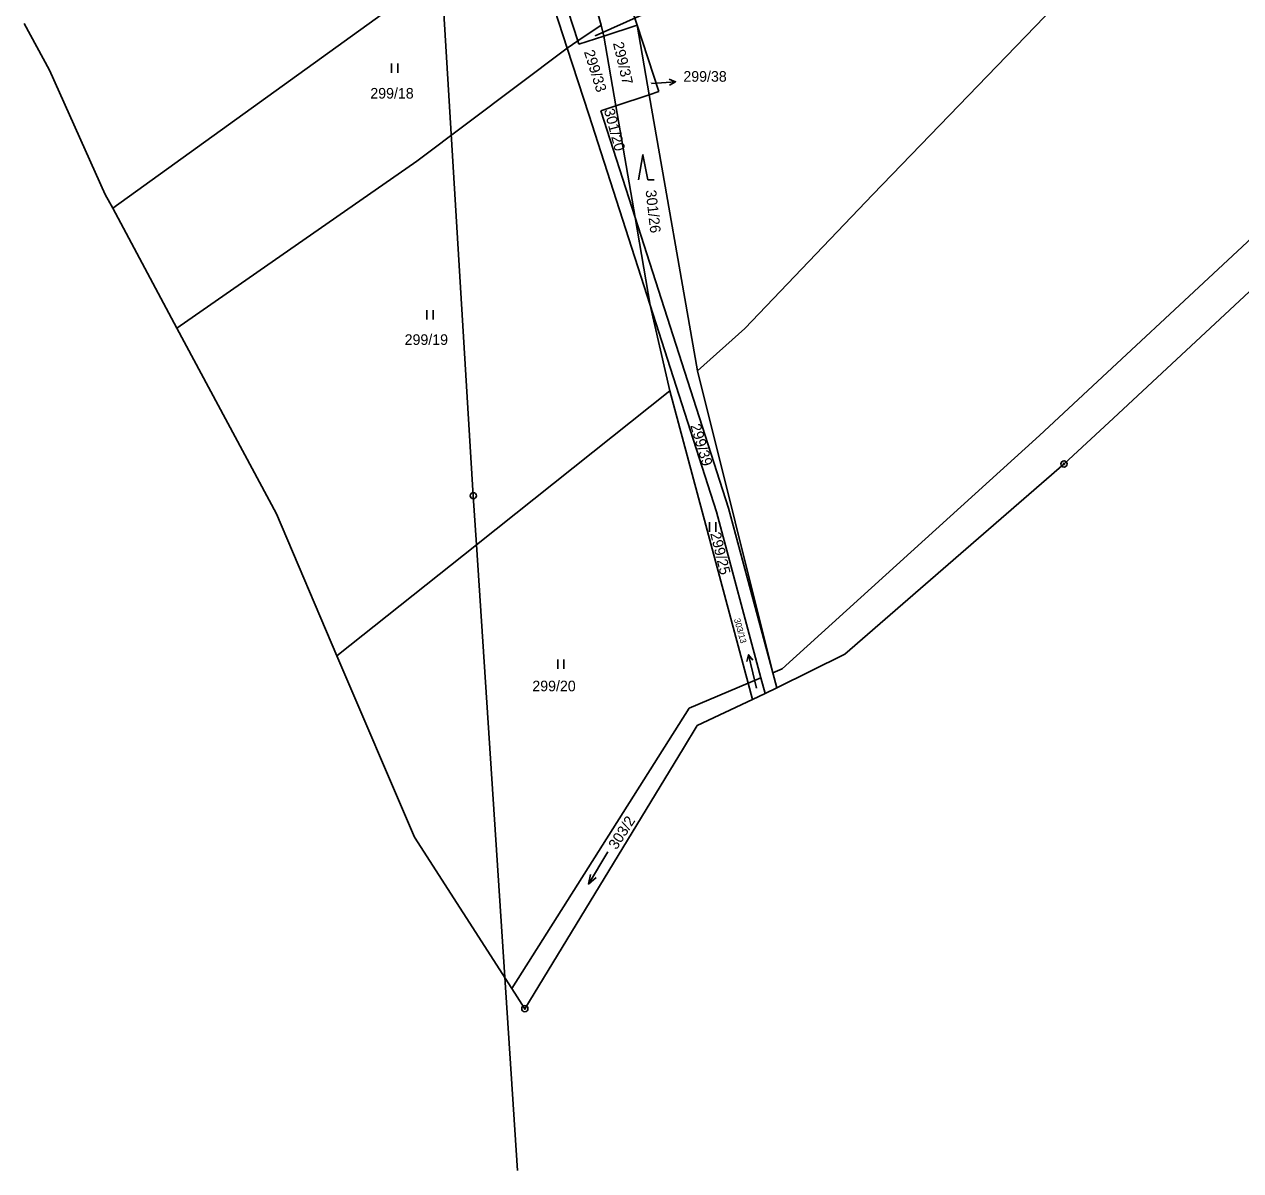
# Model space of a CAD drawing. Extents: x -762263 to -760336, y -1154405 to -1152076.
# Drawn here: x -761484.5 to -761289.6, y -1154141.1 to -1153957.5 of the extents above; entities that cross this region are included whole.
import ezdxf

# ---------------------------------------------------------------- set-up
doc = ezdxf.new("R2010")
doc.units = 0
for name, color, linetype in [('Vrstva 1', 7, 'Continuous'), ('Vrstva 12', 7, 'Continuous'), ('Vrstva 13', 7, 'Continuous'), ('Vrstva 16', 7, 'Continuous'), ('Vrstva 18', 7, 'Continuous'), ('Vrstva 24', 7, 'Continuous'), ('Vrstva 25', 7, 'Continuous'), ('Vrstva 26', 7, 'Continuous'), ('Vrstva 6', 7, 'Continuous'), ('Vrstva 62', 7, 'Continuous')]:
    doc.layers.add(name, color=color, linetype=linetype)

msp = doc.modelspace()

# ---------------------------------------------------------------- linework, layer by layer
at = {"layer": 'Vrstva 1'}
for p, q in [((-761402.87, -1153938.33), (-761395.8, -1153960.17)), ((-761404.57, -1153939.56), (-761397.52, -1153961.33)), ((-761391.66, -1153959.41), (-761386.31, -1153957.66)), ((-761386.31, -1153957.66), (-761382.82, -1153968.3)), ((-761395.8, -1153960.17), (-761395.62, -1153960.71)), ((-761395.62, -1153960.71), (-761391.66, -1153959.41)), ((-761394.04, -1153971.97), (-761397.52, -1153961.33)), ((-761389.73, -1153970.56), (-761384.36, -1153968.8)), ((-761384.36, -1153968.8), (-761382.82, -1153968.3)), ((-761392.14, -1153971.35), (-761389.73, -1153970.56)), ((-761386.64, -1153988.45), (-761392.14, -1153971.35)), ((-761394.04, -1153971.97), (-761384.21, -1154002.51)), ((-761371.67, -1154034.98), (-761386.64, -1153988.45)), ((-761321.82, -1154023.39), (-761285.43, -1153989.54)), ((-761384.21, -1154002.51), (-761373.57, -1154035.59)), ((-761363.04, -1154060.71), (-761321.82, -1154023.39)), ((-761366.48, -1154062.16), (-761373.57, -1154035.59)), ((-761364.56, -1154061.35), (-761371.67, -1154034.98)), ((-761364.56, -1154061.35), (-761363.04, -1154060.71)), ((-761363.9, -1154063.8), (-761364.56, -1154061.35)), ((-761377.98, -1154067.02), (-761368.52, -1154063.02)), ((-761368.52, -1154063.02), (-761366.48, -1154062.16)), ((-761366.48, -1154062.16), (-761365.8, -1154064.7)), ((-761406.36, -1154111.95), (-761377.98, -1154067.02))]:
    msp.add_line(p, q, dxfattribs=at)
at = {"layer": 'Vrstva 12'}
for p, q in [((-761417.88, -1153946.05), (-761412.56, -1154033.02)), ((-761412.05, -1154040.86), (-761412.56, -1154033.02)), ((-761405.49, -1154141.1), (-761412.05, -1154040.86))]:
    msp.add_line(p, q, dxfattribs=at)
at = {"layer": 'Vrstva 13'}
for p, q in [((-761480.48, -1153964.88), (-761484.5, -1153957.41)), ((-761480.48, -1153964.88), (-761471.53, -1153984.75)), ((-761470.34, -1153986.97), (-761471.53, -1153984.75)), ((-761460.04, -1154006.19), (-761470.34, -1153986.97)), ((-761309.99, -1154020.57), (-761281.02, -1153993.61)), ((-761444.11, -1154035.91), (-761460.04, -1154006.19)), ((-761317.89, -1154027.92), (-761309.99, -1154020.57)), ((-761353.03, -1154058.4), (-761317.89, -1154027.92)), ((-761434.41, -1154058.63), (-761444.11, -1154035.91)), ((-761422, -1154087.7), (-761434.41, -1154058.63)), ((-761363.9, -1154063.8), (-761353.03, -1154058.4)), ((-761365.8, -1154064.7), (-761367.82, -1154065.65)), ((-761365.8, -1154064.7), (-761363.9, -1154063.8)), ((-761367.82, -1154065.65), (-761376.66, -1154069.82)), ((-761378.86, -1154073.42), (-761376.66, -1154069.82)), ((-761404.29, -1154115.16), (-761378.86, -1154073.42)), ((-761422, -1154087.7), (-761406.36, -1154111.95)), ((-761406.36, -1154111.95), (-761404.29, -1154115.16))]:
    msp.add_line(p, q, dxfattribs=at)
at = {"layer": 'Vrstva 16'}
for p, q in [((-761393.02, -1153959.36), (-761385.48, -1153956.01)), ((-761383.98, -1153966.98), (-761383.12, -1153966.92)), ((-761380.127, -1153966.711), (-761383.12, -1153966.92)), ((-761368.45, -1154058.48), (-761367.76, -1154061.4)), ((-761367.19, -1154063.82), (-761367.76, -1154061.4))]:
    msp.add_line(p, q, dxfattribs=at)
for points in [[(-761381.16, -1153966.282), (-761380.127, -1153966.711), (-761381.09, -1153967.28)], [(-761368.706, -1154059.569), (-761368.45, -1154058.48), (-761367.733, -1154059.339)]]:
    msp.add_lwpolyline(points, dxfattribs=at)
at = {"layer": 'Vrstva 24'}
for centre, radius in [((-761317.89, -1154027.92), 0.5), ((-761317.89, -1154027.92), 0.1), ((-761404.29, -1154115.16), 0.5), ((-761404.29, -1154115.16), 0.1)]:
    msp.add_circle(centre, radius, dxfattribs=at)
at = {"layer": 'Vrstva 25'}
for p, q in [((-761425.65, -1153965.31), (-761425.65, -1153963.81)), ((-761424.65, -1153965.31), (-761424.65, -1153963.81)), ((-761420, -1154004.8), (-761420, -1154003.3)), ((-761419, -1154004.8), (-761419, -1154003.3)), ((-761374.69, -1154038.77), (-761374.69, -1154037.27)), ((-761373.69, -1154038.77), (-761373.69, -1154037.27)), ((-761399.03, -1154060.74), (-761399.03, -1154059.24)), ((-761398.03, -1154060.74), (-761398.03, -1154059.24))]:
    msp.add_line(p, q, dxfattribs=at)
for points in [[(-761386.07, -1153982.41), (-761385.37, -1153978.41), (-761384.57, -1153982.41), (-761383.57, -1153982.41)], [(-761391.009, -1154090.056), (-761394.091, -1154095.204), (-761392.891, -1154094.174)], [(-761394.091, -1154095.204), (-761393.749, -1154093.66)]]:
    msp.add_lwpolyline(points, dxfattribs=at)
at = {"layer": 'Vrstva 26'}
msp.add_circle((-761412.56, -1154033.02), 0.5, dxfattribs=at)
at = {"layer": 'Vrstva 6'}
for p, q in [((-761287.07, -1153921.16), (-761348.55, -1153984.75)), ((-761398.58, -1153935.24), (-761392.04, -1153957.63)), ((-761404.57, -1153939.56), (-761470.34, -1153986.97)), ((-761386.31, -1153957.66), (-761387.61, -1153953.52)), ((-761395.8, -1153960.17), (-761392.04, -1153957.63)), ((-761392.04, -1153957.63), (-761391.66, -1153959.41)), ((-761384.36, -1153968.8), (-761386.31, -1153957.66)), ((-761397.52, -1153961.33), (-761395.8, -1153960.17)), ((-761389.73, -1153970.56), (-761391.66, -1153959.41)), ((-761421.61, -1153979.45), (-761397.52, -1153961.33)), ((-761376.64, -1154013), (-761384.36, -1153968.8)), ((-761386.64, -1153988.45), (-761389.73, -1153970.56)), ((-761460.04, -1154006.19), (-761421.61, -1153979.45)), ((-761348.55, -1153984.75), (-761369.05, -1154006.22)), ((-761384.21, -1154002.51), (-761386.64, -1153988.45)), ((-761381.05, -1154016.23), (-761384.21, -1154002.51)), ((-761369.05, -1154006.22), (-761376.64, -1154013)), ((-761376.64, -1154013), (-761364.56, -1154061.35)), ((-761412.05, -1154040.86), (-761381.05, -1154016.23)), ((-761381.05, -1154016.23), (-761368.52, -1154063.02)), ((-761434.41, -1154058.63), (-761412.05, -1154040.86)), ((-761368.52, -1154063.02), (-761367.82, -1154065.65))]:
    msp.add_line(p, q, dxfattribs=at)

# ---------------------------------------------------------------- texts
at = {"layer": 'Vrstva 16'}
msp.add_text('299/38', height=1.7, dxfattribs=at).set_placement((-761378.893, -1153966.71))
at = {"layer": 'Vrstva 18'}
for s, height, p in [('301/21', 0.1, (-761393.233, -1153959.36)), ('299/18', 1.7, (-761429.058, -1153969.41)), ('299/38', 0.1, (-761384.233, -1153966.98)), ('299/19', 1.7, (-761423.558, -1154008.86)), ('299/20', 1.7, (-761403.096, -1154064.33)), ('303/13', 0.1, (-761367.429, -1154063.82))]:
    msp.add_text(s, height=height, dxfattribs=at).set_placement(p)
for s, rotation, p in [('299/33', 287.45292, (-761394.841, -1153961.911)), ('299/37', 283.27033, (-761390.184, -1153960.54)), ('301/20', 285.21839, (-761391.637, -1153971.251)), ('301/26', 276.45214, (-761384.955, -1153984.113)), ('299/39', 286.87997, (-761377.804, -1154021.771)), ('299/25', 283.786, (-761374.599, -1154039.068)), ('303/2', 57.29578, (-761389.603, -1154089.81))]:
    msp.add_text(s, height=1.7, rotation=rotation, dxfattribs=at).set_placement(p)
at = {"layer": 'Vrstva 62'}
msp.add_text('303/13', height=1, rotation=285.44757, dxfattribs=at).set_placement((-761370.79, -1154052.8))

doc.saveas('drawing.dxf')
